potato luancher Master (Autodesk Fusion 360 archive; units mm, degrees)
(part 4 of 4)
sketch "cap_nut .25" plane through (1.5875, 0, 0) normal (-1, 0, 0) x axis (0, -1, 0)
  line L1 (-415.0627, 96.1751) -> (-419.0927, 96.1751)
  line L2 (-410.7414, 131.3694) -> (-415.0627, 96.1751)
  line L3 (-322.4775, 131.3694) -> (-410.7414, 131.3694)
  line L4 (-322.4775, 135.3707) -> (-322.4775, 131.3694)
  line L5 (-330.8961, 135.3707) -> (-322.4775, 135.3707)
  line L6 (-363.9219, 140.5486) -> (-363.9219, 135.3707)
  line L7 (-340.0129, 144.3077) -> (-356.7396, 146.7561)
  line L8 (-329.3961, 159.7411) -> (-329.3961, 153.4836)
  line L9 (-332.3961, 159.7411) -> (-329.3961, 159.7411)
  line L10 (-332.3961, 153.4836) -> (-332.3961, 159.7411)
  line L11 (-356.3051, 149.7245) -> (-339.5784, 147.2761)
  line L12 (-363.9219, 159.7411) -> (-363.9219, 158.5373)
  line L13 (-366.9219, 159.7411) -> (-363.9219, 159.7411)
  line L14 (-366.9219, 158.5373) -> (-366.9219, 159.7411)
  line L15 (-391.2654, 147.2761) -> (-374.5387, 149.7245)
  line L16 (-398.4477, 159.7411) -> (-398.4477, 153.4836)
  line L17 (-401.4477, 159.7411) -> (-398.4477, 159.7411)
  line L18 (-401.4477, 153.4836) -> (-401.4477, 159.7411)
  line L19 (-425.465, 149.168) -> (-408.6888, 147.0857)
  line L20 (-431.7898, 159.7411) -> (-432.0453, 157.5478)
  line L21 (-435.0251, 157.8949) -> (-434.8326, 159.5478)
  line L22 (-445.2444, 150.2873) -> (-443.57, 150.2873)
  line L23 (-443.57, 147.2873) -> (-445.7958, 147.2873)
  line L24 (-439.8464, 116.4962) -> (-437.106, 140.0269)
  line L25 (-450.3271, 110.1718) -> (-448.1574, 109.9191)
  line L26 (-448.5045, 106.9392) -> (-450.1574, 107.1317)
  line L27 (-418.2043, 103.4104) -> (-430.6365, 104.8583)
  line L28 (-419.0927, 96.1751) -> (-418.2043, 103.4104)
  line L29 (-434.1262, 139.6798) -> (-436.8666, 116.1492)
  line L30 (-409.0583, 144.1086) -> (-425.8345, 146.1909)
  line L31 (-374.1042, 146.7561) -> (-390.8309, 144.3077)
  line L32 (-366.9219, 135.3707) -> (-366.9219, 140.5486)
  line L33 (-399.9477, 135.3707) -> (-366.9219, 135.3707)
  line L34 (-414.2801, 135.3707) -> (-399.9477, 135.3707)
  line L35 (-417.8387, 106.3881) -> (-414.2801, 135.3707)
  line L36 (-430.2894, 107.8382) -> (-417.8387, 106.3881)
  line L37 (-433.4597, 110.8166) -> (-433.4597, 103.9608)
  line L38 (-439.397, 114.2444) -> (-433.4597, 110.8166)
  line L39 (-445.3342, 110.8166) -> (-439.397, 114.2444)
  line L40 (-445.3342, 103.9608) -> (-445.3342, 110.8166)
  line L41 (-439.397, 100.5329) -> (-445.3342, 103.9608)
  line L42 (-433.4597, 103.9608) -> (-439.397, 100.5329)
  line L43 (-432.5812, 159.7411) -> (-431.7898, 159.7411)
  line L44 (-445.7958, 147.2873) -> (-445.6908, 148.1427)
  line L45 (-428.6384, 152.2152) -> (-428.6384, 145.3595)
  line L46 (-434.5757, 155.6431) -> (-428.6384, 152.2152)
  line L47 (-440.5129, 152.2152) -> (-434.5757, 155.6431)
  line L48 (-440.5129, 145.3595) -> (-440.5129, 152.2152)
  line L49 (-434.5757, 141.9316) -> (-440.5129, 145.3595)
  line L50 (-428.6384, 145.3595) -> (-434.5757, 141.9316)
  line L51 (-394.0104, 147.9171) -> (-394.0104, 141.0614)
  line L52 (-399.9477, 151.345) -> (-394.0104, 147.9171)
  line L53 (-405.8849, 147.9171) -> (-399.9477, 151.345)
  line L54 (-405.8849, 141.0614) -> (-405.8849, 147.9171)
  line L55 (-399.9477, 137.6335) -> (-405.8849, 141.0614)
  line L56 (-394.0104, 141.0614) -> (-399.9477, 137.6335)
  line L57 (-359.4847, 146.1151) -> (-365.4219, 142.6872)
  line L58 (-359.4847, 152.9708) -> (-359.4847, 146.1151)
  line L59 (-365.4219, 156.3987) -> (-359.4847, 152.9708)
  line L60 (-371.3592, 152.9708) -> (-365.4219, 156.3987)
  line L61 (-371.3592, 146.1151) -> (-371.3592, 152.9708)
  line L62 (-365.4219, 142.6872) -> (-371.3592, 146.1151)
  line L63 (-324.9589, 147.9171) -> (-324.9589, 141.0614)
  line L64 (-330.8961, 151.345) -> (-324.9589, 147.9171)
  line L65 (-336.8334, 147.9171) -> (-330.8961, 151.345)
  line L66 (-336.8334, 141.0614) -> (-336.8334, 147.9171)
  line L67 (-330.8961, 137.6335) -> (-336.8334, 141.0614)
  line L68 (-324.9589, 141.0614) -> (-330.8961, 137.6335)
  line L69 (-363.9219, 135.3707) -> (-330.8961, 135.3707)
  arc A1 centre (-365.4219, 149.543) radius 9.1186 clockwise from (-356.7396, 146.7561) to (-363.9219, 140.5486)
  arc A2 centre (-330.8961, 144.4893) radius 9.1186 clockwise from (-330.8961, 135.3707) to (-340.0129, 144.3077)
  arc A3 centre (-330.8961, 144.4893) radius 9.1186 clockwise from (-329.3961, 153.4836) to (-330.8961, 135.3707)
  arc A4 centre (-330.8961, 144.4893) radius 9.1186 clockwise from (-339.5784, 147.2761) to (-332.3961, 153.4836)
  arc A5 centre (-365.4219, 149.543) radius 9.1186 clockwise from (-363.9219, 158.5373) to (-356.3051, 149.7245)
  arc A6 centre (-365.4219, 149.543) radius 9.1186 clockwise from (-374.5387, 149.7245) to (-366.9219, 158.5373)
  arc A7 centre (-399.9477, 144.4893) radius 9.1186 clockwise from (-398.4477, 153.4836) to (-391.2654, 147.2761)
  arc A8 centre (-399.9477, 144.4893) radius 9.1186 clockwise from (-408.6888, 147.0857) to (-401.4477, 153.4836)
  arc A9 centre (-434.5757, 148.7873) radius 9.1186 clockwise from (-432.0453, 157.5478) to (-425.465, 149.168)
  arc A10 centre (-432.5812, 146.5331) radius 13.208 clockwise from (-434.8326, 159.5478) to (-432.5812, 159.7411)
  arc A11 centre (-434.5757, 148.7873) radius 9.1186 clockwise from (-443.57, 150.2873) to (-435.0251, 157.8949)
  arc A12 centre (-432.5812, 146.5331) radius 13.208 clockwise from (-445.6908, 148.1427) to (-445.2444, 150.2873)
  arc A13 centre (-434.5757, 148.7873) radius 9.1186 clockwise from (-437.106, 140.0269) to (-443.57, 147.2873)
  arc A14 centre (-439.397, 107.3887) radius 9.1186 clockwise from (-448.1574, 109.9191) to (-439.8464, 116.4962)
  arc A15 centre (-437.1427, 109.3831) radius 13.208 clockwise from (-450.1574, 107.1317) to (-450.3271, 110.1718)
  arc A16 centre (-439.397, 107.3887) radius 9.1186 clockwise from (-430.6365, 104.8583) to (-448.5045, 106.9392)
  circle C1 centre (-434.5757, 148.7873) radius 3.325
  arc A17 centre (-434.5757, 148.7873) radius 9.1186 clockwise from (-425.8345, 146.1909) to (-434.1262, 139.6798)
  arc A18 centre (-399.9477, 144.4893) radius 9.1186 clockwise from (-399.9477, 135.3707) to (-409.0583, 144.1086)
  arc A19 centre (-399.9477, 144.4893) radius 9.1186 clockwise from (-390.8309, 144.3077) to (-399.9477, 135.3707)
  arc A20 centre (-365.4219, 149.543) radius 9.1186 clockwise from (-366.9219, 140.5486) to (-374.1042, 146.7561)
  arc A21 centre (-439.397, 107.3887) radius 9.1186 clockwise from (-436.8666, 116.1492) to (-430.2894, 107.8382)
  circle C2 centre (-399.9477, 144.4893) radius 3.325
  circle C3 centre (-365.4219, 149.543) radius 3.325
  circle C4 centre (-439.397, 107.3887) radius 3.325
  circle C5 centre (-330.8961, 144.4893) radius 3.325
  point P46 (-439.397, 107.3887)
  point P71 (-439.397, 107.3887)
  point P34 (-434.5757, 148.7873)
  point P80 (-434.5757, 148.7873)
  point P27 (-399.9477, 144.4893)
  point P87 (-399.9477, 144.4893)
  point P11 (-365.4219, 149.543)
  point P94 (-365.4219, 149.543)
  point P13 (-330.8961, 144.4893)
  point P101 (-330.8961, 144.4893)
  coincident P46 P71
  vertical L37
  coincident P34 P80
  coincident P27 P87
  coincident P11 P94
  coincident P13 P101
  equal L39 L47
  equal L46 L53
  equal L52 L60
  equal L58 L66
  vertical L45
  vertical L51
  vertical L61
  vertical L66
  dimension "d673" distance L39 L42 = 11.8745 (= "( ( 7 / 16 ) * 1 in ) + 0.030 in")
extrude "Extrude17" cut sketch "cap_nut .25" profile of C1 C2 C3 C4 C5 L37 L38 L39 L40 L41 L42 L45 L46 L47 L48 L49 L50 L51 L52 L53 L54 L55 L56 L57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 blind -66.04 from offset -3.9624 (= "( -0.312 / 2 ) * 1 in")
sketch "Sketch12" plane through (-1.5875, 0, 0) normal (1, 0, 0) x axis (0, 1, 0)
  line L1 (436.8666, 116.1492) -> (434.1262, 139.6798)
  line L2 (417.8387, 106.3881) -> (430.2894, 107.8382)
  line L3 (414.2801, 135.3707) -> (417.8387, 106.3881)
  line L4 (399.9477, 135.3707) -> (414.2801, 135.3707)
  line L5 (366.9219, 135.3707) -> (399.9477, 135.3707)
  line L6 (366.9219, 140.5486) -> (366.9219, 135.3707)
  line L7 (390.8309, 144.3077) -> (374.1042, 146.7561)
  line L8 (425.8345, 146.1909) -> (409.0583, 144.1086)
  line L9 (433.6818, 169.4293) -> (435.0251, 157.8949)
  line L10 (433.6818, 169.4293) -> (452.8382, 169.4293)
  line L11 (455.1885, 150.2873) -> (452.8382, 169.4293)
  line L12 (443.57, 150.2873) -> (455.1885, 150.2873)
  line L13 (455.5569, 147.2873) -> (443.57, 147.2873)
  line L14 (459.9761, 111.2955) -> (455.5569, 147.2873)
  line L15 (448.1574, 109.9191) -> (459.9761, 111.2955)
  line L16 (437.106, 140.0269) -> (439.8464, 116.4962)
  line L17 (356.7396, 146.7561) -> (340.0129, 144.3077)
  line L18 (363.9219, 135.3707) -> (363.9219, 140.5486)
  line L19 (330.8961, 135.3707) -> (363.9219, 135.3707)
  line L20 (322.4775, 135.3707) -> (330.8961, 135.3707)
  line L21 (322.4775, 131.3694) -> (322.4775, 135.3707)
  line L22 (410.7414, 131.3694) -> (322.4775, 131.3694)
  line L23 (415.1763, 95.25) -> (410.7414, 131.3694)
  line L24 (419.2063, 95.25) -> (415.1763, 95.25)
  line L25 (418.2043, 103.4104) -> (419.2063, 95.25)
  line L26 (430.6365, 104.8583) -> (418.2043, 103.4104)
  line L27 (460.3417, 108.3178) -> (448.5045, 106.9392)
  line L28 (461.9462, 95.25) -> (460.3417, 108.3178)
  line L29 (465.9763, 95.25) -> (461.9462, 95.25)
  line L30 (456.3769, 173.4306) -> (465.9763, 95.25)
  line L31 (456.3769, 173.4306) -> (405.5769, 173.4306)
  line L32 (322.4775, 173.4306) -> (405.5769, 173.4306)
  line L33 (322.4775, 169.45) -> (322.4775, 173.4306)
  line L34 (322.8085, 169.45) -> (322.4775, 169.45)
  line L35 (322.8085, 169.4293) -> (322.8085, 169.45)
  line L36 (329.3961, 169.4293) -> (322.8085, 169.4293)
  line L37 (329.3961, 153.4836) -> (329.3961, 169.4293)
  line L38 (332.3961, 169.4293) -> (332.3961, 153.4836)
  line L39 (363.9219, 169.4293) -> (332.3961, 169.4293)
  line L40 (363.9219, 158.5373) -> (363.9219, 169.4293)
  line L41 (339.5784, 147.2761) -> (356.3051, 149.7245)
  line L42 (374.5387, 149.7245) -> (391.2654, 147.2761)
  line L43 (366.9219, 169.4293) -> (366.9219, 158.5373)
  line L44 (398.4477, 169.4293) -> (366.9219, 169.4293)
  line L45 (398.4477, 153.4836) -> (398.4477, 169.4293)
  line L46 (408.6888, 147.0857) -> (425.465, 149.168)
  line L47 (401.4477, 169.4293) -> (401.4477, 153.4836)
  line L48 (410.0982, 169.4293) -> (401.4477, 169.4293)
  line L49 (410.0982, 169.4293) -> (430.6615, 169.4293)
  line L50 (432.0453, 157.5478) -> (430.6615, 169.4293)
  circle C1 centre (434.5757, 148.7873) radius 3.325
  arc A1 centre (439.397, 107.3887) radius 9.1186 clockwise from (430.2894, 107.8382) to (436.8666, 116.1492)
  arc A2 centre (365.4219, 149.543) radius 9.1186 clockwise from (374.1042, 146.7561) to (366.9219, 140.5486)
  arc A3 centre (399.9477, 144.4893) radius 9.1186 clockwise from (399.9477, 135.3707) to (390.8309, 144.3077)
  arc A4 centre (399.9477, 144.4893) radius 9.1186 clockwise from (409.0583, 144.1086) to (399.9477, 135.3707)
  arc A5 centre (434.5757, 148.7873) radius 9.1186 clockwise from (434.1262, 139.6798) to (425.8345, 146.1909)
  arc A6 centre (434.5757, 148.7873) radius 9.1186 clockwise from (435.0251, 157.8949) to (443.57, 150.2873)
  arc A7 centre (434.5757, 148.7873) radius 9.1186 clockwise from (443.57, 147.2873) to (437.106, 140.0269)
  arc A8 centre (439.397, 107.3887) radius 9.1186 clockwise from (439.8464, 116.4962) to (448.1574, 109.9191)
  circle C2 centre (399.9477, 144.4893) radius 3.325
  arc A9 centre (330.8961, 144.4893) radius 9.1186 clockwise from (340.0129, 144.3077) to (330.8961, 135.3707)
  arc A10 centre (365.4219, 149.543) radius 9.1186 clockwise from (363.9219, 140.5486) to (356.7396, 146.7561)
  arc A11 centre (439.397, 107.3887) radius 9.1186 clockwise from (448.5045, 106.9392) to (430.6365, 104.8583)
  arc A12 centre (330.8961, 144.4893) radius 9.1186 clockwise from (330.8961, 135.3707) to (329.3961, 153.4836)
  arc A13 centre (365.4219, 149.543) radius 9.1186 clockwise from (356.3051, 149.7245) to (363.9219, 158.5373)
  arc A14 centre (330.8961, 144.4893) radius 9.1186 clockwise from (332.3961, 153.4836) to (339.5784, 147.2761)
  circle C3 centre (365.4219, 149.543) radius 3.325
  circle C4 centre (439.397, 107.3887) radius 3.325
  arc A15 centre (399.9477, 144.4893) radius 9.1186 clockwise from (391.2654, 147.2761) to (398.4477, 153.4836)
  arc A16 centre (365.4219, 149.543) radius 9.1186 clockwise from (366.9219, 158.5373) to (374.5387, 149.7245)
  circle C5 centre (330.8961, 144.4893) radius 3.325
  arc A17 centre (434.5757, 148.7873) radius 9.1186 clockwise from (425.465, 149.168) to (432.0453, 157.5478)
  arc A18 centre (399.9477, 144.4893) radius 9.1186 clockwise from (401.4477, 153.4836) to (408.6888, 147.0857)
  circle C6 centre (330.8961, 144.4893) radius 5.0245
  circle C7 centre (365.4219, 149.543) radius 5.0245
  circle C8 centre (399.9477, 144.4893) radius 5.0245
  circle C9 centre (434.5757, 148.7873) radius 5.0245
  circle C10 centre (439.397, 107.3887) radius 5.0245
  concentric A9 C6
  concentric A2 C7
  concentric A3 C8
  concentric C1 C9
  concentric A1 C10
  equal C7 C8
  equal C8 C9
  equal C9 C10
  equal C6 C7
  dimension "d678" diameter C6 = 10.049 (= "( ( 3 / 8 ) * 1 in ) + 0.06 in - 1 mm")
extrude "Extrude18" cut sketch "Sketch12" profile of C1 C2 C3 C4 C5 C6 C7 C8 C9 C10 blind -35.56 from offset -3.9624 (= "( -0.312 / 2 ) * 1 in")
step "Screw1"
joint "Assemble1" alignAngle 0 alignOffsetX 0 alignOffsetY 0 alignOffsetZ 0
step "Screw2"
joint "Assemble2" alignAngle 0 alignOffsetX 0 alignOffsetY 0 alignOffsetZ 0
step "Screw3"
joint "Assemble3" alignAngle 0 alignOffsetX 0 alignOffsetY 0 alignOffsetZ 0
step "Screw4"
joint "Assemble4" alignAngle 0 alignOffsetX 0 alignOffsetY 0 alignOffsetZ 0
step "Screw5"
joint "Assemble5" alignAngle 0 alignOffsetX 0 alignOffsetY 0 alignOffsetZ 0
sketch "Sketch7" plane through (-1.5875, 0, 0) normal (-1, 0, 0) x axis (0, -1, 0)
  line L1 (-347.7775, 159.7411) -> (-322.7775, 159.7411)
  line L2 (-347.7775, 165.0751) -> (-347.7775, 159.7411)
  line L3 (-322.7775, 165.0751) -> (-347.7775, 165.0751)
  line L4 (-322.7775, 173.45) -> (-322.7775, 165.0751)
  line L5 (-456.3745, 173.45) -> (-322.7775, 173.45)
  line L6 (-466.756, 88.9) -> (-456.3745, 173.45)
  line L7 (-415.956, 88.9) -> (-466.756, 88.9)
  line L8 (-410.7438, 131.35) -> (-415.956, 88.9)
  line L9 (-322.7775, 131.35) -> (-410.7438, 131.35)
  line L10 (-322.7775, 159.7411) -> (-322.7775, 131.35)
  circle C1 centre (-434.5757, 148.7873) radius 3.175
  circle C2 centre (-399.9477, 144.4893) radius 3.175
  circle C3 centre (-365.4219, 149.543) radius 3.175
  circle C4 centre (-330.8961, 144.4893) radius 3.175
  circle C5 centre (-439.397, 107.3887) radius 3.175
  point P12 (-434.5757, 148.7873)
  point P17 (-434.5757, 148.7873)
  point P13 (-399.9477, 144.4893)
  point P18 (-399.9477, 144.4893)
  point P15 (-365.4219, 149.543)
  point P19 (-365.4219, 149.543)
  point P16 (-330.8961, 144.4893)
  point P20 (-330.8961, 144.4893)
  point P14 (-439.397, 107.3887)
  point P21 (-439.397, 107.3887)
  coincident P12 P17
  coincident P13 P18
  coincident P15 P19
  coincident P16 P20
  coincident P14 P21
  dimension "d702" diameter C1 = 6.35
  dimension "d703" diameter C2 = 6.35
  dimension "d704" diameter C3 = 6.35
  dimension "d705" diameter C4 = 6.35
  dimension "d706" diameter C5 = 6.35
extrude "Extrude2" cut sketch "Sketch7" profile of C1 C2 C3 C4 C5 against normal blind 3.175
sketch "fwd upper hole" plane through (0, 0, 0) normal (1, 0, 0) x axis (0, 1, 0)
  line L1 (322.4775, 173.45) -> (322.4775, 169.45)
  line L2 (250.2367, 173.45) -> (322.4775, 173.45)
  line L3 (250.2367, 116.35) -> (250.2367, 173.45)
  line L4 (272.2367, 116.35) -> (250.2367, 116.35)
  line L5 (276.256, 131.35) -> (272.2367, 116.35)
  line L6 (277.081, 131.35) -> (276.256, 131.35)
  line L7 (275.635, 135.35) -> (277.081, 131.35)
  line L8 (273.1866, 135.35) -> (275.635, 135.35)
  line L9 (269.1674, 120.35) -> (273.1866, 135.35)
  line L10 (254.2367, 120.35) -> (269.1674, 120.35)
  line L11 (254.2367, 169.45) -> (254.2367, 120.35)
  line L12 (322.4775, 169.45) -> (254.2367, 169.45)
  line L13 (315.5775, 141.85) -> (319.7775, 137.65)
  line L14 (296.5763, 141.85) -> (315.5775, 141.85)
  line L15 (279.0207, 162.9256) -> (296.5763, 141.85)
  line L16 (263.8509, 141.85) -> (270.1342, 165.3063)
  line L17 (260.0435, 127.6406) -> (263.8509, 141.85)
  line L18 (272.0357, 136.85) -> (268.93, 125.2594)
  line L19 (278.9967, 136.85) -> (272.0357, 136.85)
  line L20 (278.9967, 123.4258) -> (278.9967, 136.85)
  line L21 (313.4688, 135.65) -> (313.4688, 131.35)
  line L22 (319.7775, 135.65) -> (313.4688, 135.65)
  line L23 (319.7775, 137.65) -> (319.7775, 135.65)
  line L24 (287.4207, 168.3994) -> (287.4207, 165.0507)
  line L25 (284.5207, 170.0737) -> (287.4207, 168.3994)
  line L26 (281.6207, 168.3994) -> (284.5207, 170.0737)
  line L27 (281.6207, 165.0507) -> (281.6207, 168.3994)
  line L28 (284.5207, 163.3764) -> (281.6207, 165.0507)
  line L29 (287.4207, 165.0507) -> (284.5207, 163.3764)
  line L30 (332.3961, 159.7411) -> (332.3961, 165.0751)
  line L31 (329.3961, 159.7411) -> (332.3961, 159.7411)
  line L32 (329.3961, 165.0751) -> (329.3961, 159.7411)
  line L33 (332.3961, 165.0751) -> (329.3961, 165.0751)
  line L34 (239.3698, 165.0751) -> (329.3961, 165.0751)
  circle C1 centre (284.5207, 166.7251) radius 4.5
  circle C2 centre (264.4867, 126.45) radius 1.65
  arc A1 centre (264.4867, 126.45) radius 39.2645 clockwise from (270.1342, 165.3063) to (279.0207, 162.9256)
  arc A2 centre (264.4867, 126.45) radius 4.6 clockwise from (268.93, 125.2594) to (260.0435, 127.6406)
  arc A3 centre (274.4187, 51.1532) radius 72.4175 clockwise from (278.9967, 123.4258) to (311.5111, 113.35)
  arc A4 centre (229.7424, 131.35) radius 83.7264 clockwise from (313.4688, 131.35) to (311.5111, 113.35)
  circle C3 centre (284.5207, 166.7251) radius 1.65
  circle C4 centre (284.5207, 166.7251) radius 3
  point P33 (284.5207, 166.7251)
  point P40 (284.5207, 166.7251)
  point P44 (329.3961, 165.0751)
  point P45 (329.3961, 165.0751)
  point P48 (284.5207, 166.7251)
  point P14 (284.5207, 166.7251)
  point P47 (279.0207, 162.9256)
  concentric C1 C3
  coincident P33 P40
  vertical L24
  coincident P44 P45
  perpendicular L3 L34
  tangent C3 L34
  coincident P40 P48
  dimension "d758" diameter C1 = 9
  dimension "d759" diameter C3 = 3.3
  dimension "d762" distance P40 L29 = 2.9 (= "5.8 mm / 2")
  dimension "d767" distance P14 P47 = 5.5 (= "( d758 / 2 ) + 1 mm")
  dimension "d770" diameter C4 = 6
extrude "Extrude19" cut sketch "fwd upper hole" profile of C3 distance 63.5
extrude "Extrude20" add sketch "fwd upper hole" profile of L12 C1 C3 L24 L25 L26 L27 L28 L29 blind -13.248 (= "-0.62 in + 2.5 mm") from offset -2.5
extrude "Extrude21" add sketch "fwd upper hole" profile of L12 C1 C3 L24 L25 L26 L27 L28 L29 blind 12.74 (= "0.60 in - 2.5 mm") from offset 2.5
extrude "Extrude22" cut sketch "fwd upper hole" profile of L12 C3 L24 L25 L26 L27 L28 L29 C4 blind 27.178 from offset 11.5 (= "23 / 2 * 1 mm")
extrude "Extrude23" cut sketch "fwd upper hole" profile of L12 C3 L24 L25 L26 L27 L28 L29 C4 blind -38.1 from offset -11.5 (= "-23 / 2 * 1 mm")
work_plane "WorkPlane26" AlongDistance 173.4312
sketch "rel. arm" plane through (-21.6421, 0, 39.0435) normal (0.4848, 0, -0.8746) x axis (0, 1, 0)
  line L1 (-18.2143, -41.7968) -> (-43.5756, -54.6337)
  line L2 (-46.6067, -41.9337) -> (-23.9497, -30.4657)
  line L3 (-69.7366, -42.4813) -> (-48.9008, -42.4813)
  line L4 (-68.326, -34.4813) -> (-69.7366, -42.4813)
  line L5 (-45.8698, -55.1813) -> (-69.626, -55.1813)
  line L6 (-53.3478, -62.9923) -> (-49.4885, -84.8797)
  line L7 (46.7086, -45.3497) -> (-53.3478, -62.9923)
  line L8 (50.568, -67.237) -> (46.7086, -45.3497)
  line L9 (-49.4885, -84.8797) -> (50.568, -67.237)
  line L10 (-55.5532, -50.4852) -> (-53.3478, -62.9923)
  line L11 (-34.5873, -59.6843) -> (-36.7926, -47.1773)
  line L12 (-34.5873, -59.6843) -> (-49.4885, -84.8797)
  arc A1 centre (-45.8698, -50.1012) radius 5.08 clockwise from (-43.5756, -54.6337) to (-45.8698, -55.1813)
  arc A2 centre (-48.9008, -37.4013) radius 5.08 clockwise from (-46.6067, -41.9337) to (-48.9008, -42.4813)
  arc A3 centre (-68.326, -50.7312) radius 16.25 clockwise from (-82.326, -42.4813) to (-68.326, -34.4813)
  arc A4 centre (-69.626, -42.4813) radius 12.7 clockwise from (-69.626, -55.1813) to (-82.326, -42.4813)
  circle C1 centre (-46.1729, -48.8313) radius 3.175
  circle C2 centre (-46.1729, -48.8313) radius 9.525
  arc A5 centre (-27.3278, -49.3167) radius 8.9495 clockwise from (-25.7737, -58.1302) to (-36.1413, -50.8708)
  arc A6 centre (-21.082, -36.1313) radius 6.35 clockwise from (-23.9497, -30.4657) to (-18.2143, -41.7968)
  circle C3 centre (-21.082, -36.1313) radius 3.175
  point P22 (-55.5532, -50.4852)
  point P23 (-36.7926, -47.1773)
  point P24 (-34.5873, -59.6843)
  point P27 (-25.7737, -58.1302)
  point P26 (-36.1413, -50.8708)
  point P17 (-49.4885, -84.8797)
  point P18 (-53.3478, -62.9923)
  point P21 (-46.1729, -48.8313)
  point P20 (50.568, -67.237)
  perpendicular L6 L7
  parallel L6 L8
  parallel L7 L9
  concentric C1 C2
  coincident C2 P22
  perpendicular L7 L10
  tangent C2 L10
  coincident C2 P23
  coincident L7 P24
  tangent C2 L11
  perpendicular L7 L11
  coincident L7 P27
  coincident L11 P26
  tangent L11 A5
  tangent L7 A5
  coincident L1 P26
  dimension "d713" distance P17 P18 = 22.225
  dimension "d714" diameter C2 = 19.05
  dimension "d715" distance L7 P21 = 12.7
  dimension "d716" angle L5 L10 = 100
  dimension "d717" distance P17 P20 = 101.6
face "Face1" sketch "rel. arm"
fillet "Fillet1" radius 27.94
position "Position12"
sketch "Sketch59" plane through (-21.0604, 0, 37.9939) normal (-0.4848, 0, 0.8746) x axis (0, -1, 0)
  line L1 (55.5532, -50.4852) -> (54.3402, -57.3641)
  line L2 (36.1413, -50.8708) -> (36.7926, -47.1773)
  line L3 (-46.7086, -45.3497) -> (25.7737, -58.1302)
  line L4 (-50.568, -67.237) -> (-46.7086, -45.3497)
  line L5 (21.973, -80.0279) -> (-50.568, -67.237)
  circle C1 centre (46.1729, -48.8313) radius 3.175
  arc A1 centre (26.8247, -52.5124) radius 27.94 clockwise from (54.3402, -57.3641) to (21.973, -80.0279)
  arc A2 centre (46.1729, -48.8313) radius 9.525 clockwise from (36.7926, -47.1773) to (55.5532, -50.4852)
  arc A3 centre (27.3278, -49.3167) radius 8.9495 clockwise from (36.1413, -50.8708) to (25.7737, -58.1302)
  circle C2 centre (46.1729, -48.8313) radius 9.525
  circle C3 centre (46.1729, -48.8313) radius 3.475
  concentric C1 C2
  dimension "d724" = 0.3
place_component sketch "Sketch59"
extrude "Extrude1" new body sketch "Sketch59" profile of A2 C2 C3 along normal blind 1.2
sketch "rel spring anchor" plane through (-64.597, 13.023, -35.8067) normal (-0.8613, 0.1736, -0.4774) x axis (-0.1976, -0.9803, 0)
  line L1 (39.5345, 39.8359) -> (39.2303, 36.6755)
  line L2 (-33.7866, 46.8934) -> (39.5345, 39.8359)
  line L3 (-34.0908, 43.733) -> (-33.7866, 46.8934)
  line L4 (39.2303, 36.6755) -> (-34.0908, 43.733)
  line L5 (21.4358, 41.578) -> (22.1659, 49.1629)
  line L6 (12.1191, 52.7294) -> (19.8382, 51.9864)
  line L7 (4.4452, 46.4031) -> (12.1191, 52.7294)
  line L8 (4.141, 43.2427) -> (4.4452, 46.4031)
  circle C1 centre (19.5903, 49.4108) radius 1
  circle C2 centre (19.5903, 49.4108) radius 2.5875
  point P9 (21.4358, 41.578)
  point P12 (4.141, 43.2427)
  point P8 (19.8382, 51.9864)
  point P7 (22.1659, 49.1629)
  point P6 (19.5903, 49.4108)
  point P11 (4.4452, 46.4031)
  coincident L2 P9
  perpendicular L2 L5
  perpendicular L5 L6
  coincident L2 P12
  perpendicular L2 L8
  coincident P8 C2
  tangent L6 C2
  coincident P7 C2
  tangent L5 C2
  dimension "d734" angle L7 L8 = 135
  dimension "d735" = 1.5875 (= "( 1 / 16 ) * 1 in")
  dimension "d751" distance L2 P6 = 7.62
  dimension "d752" diameter C1 = 2
  dimension "d753" distance P11 P12 = 3.175
place_component sketch "rel spring anchor"
face "Face1" sketch "rel spring anchor"
sketch "arming handle" plane through (-29.1846, 0, 52.6504) normal (0.4848, 0, -0.8746) x axis (0, 1, 0)
  line L1 (-118.3323, -14.605) -> (-207.2323, -14.605)
  line L2 (-118.3323, 14.605) -> (-118.3323, -14.605)
  line L3 (-207.2323, 14.605) -> (-118.3323, 14.605)
  line L4 (-207.2323, -14.605) -> (-207.2323, 14.605)
  line L5 (22.5, 0) -> (1.75, 0)
  line L6 (-123.3323, 9.605) -> (-123.3323, -9.605)
  line L7 (-205.0949, 9.605) -> (-123.3323, 9.605)
  line L8 (-123.3323, -9.605) -> (-205.0949, -9.605)
  line L9 (-108.8073, 14.605) -> (-118.3323, 14.605)
  line L10 (-108.8073, -14.605) -> (-108.8073, 14.605)
  line L11 (-118.3323, -14.605) -> (-108.8073, -14.605)
  line L12 (-118.3323, 14.605) -> (-118.3323, -14.605)
  line L13 (-136.0323, -9.605) -> (-136.0323, 9.605)
  line L14 (-141.0323, -9.605) -> (-141.0323, 9.605)
  line L15 (-192.3949, -9.605) -> (-192.3949, 9.605)
  line L16 (-187.3949, -9.605) -> (-187.3949, 9.605)
  line L17 (-161.7136, -9.605) -> (-161.7136, 9.605)
  line L18 (-166.7136, -9.605) -> (-166.7136, 9.605)
  line L19 (-187.3949, 0) -> (-166.7136, 0)
  line L20 (-141.0323, 0) -> (-161.7136, 0)
  circle C1 centre (-95.6445, -13.1559) radius 1.61
  circle C2 centre (-38.0048, 0) radius 1.61
  circle C3 centre (-95.6445, 13.1559) radius 1.61
  circle C4 centre (-75.0731, -29.561) radius 1.61
  circle C5 centre (-49.421, 23.7061) radius 1.61
  circle C6 centre (-75.0731, 29.561) radius 1.61
  circle C7 centre (-49.421, -23.7061) radius 1.61
  circle C8 centre (-68.326, 0) radius 20.1613
  circle C9 centre (-68.326, 0) radius 40.4813
  circle C10 centre (-95.6445, -13.1559) radius 1.61
  circle C11 centre (-38.0048, 0) radius 1.61
  circle C12 centre (-95.6445, 13.1559) radius 1.61
  circle C13 centre (-75.0731, -29.561) radius 1.61
  circle C14 centre (-49.421, 23.7061) radius 1.61
  circle C15 centre (-75.0731, 29.561) radius 1.61
  circle C16 centre (-49.421, -23.7061) radius 1.61
  circle C17 centre (-68.326, 0) radius 20.1613
  circle C18 centre (-68.326, 0) radius 40.4813
  circle C19 centre (-68.326, 0) radius 40.4813
  arc A1 centre (-193.6115, 0) radius 19.9707 clockwise from (-207.2323, -14.605) to (-207.2323, 14.605)
  arc A2 centre (-193.6115, 0) radius 14.9707 clockwise from (-205.0949, -9.605) to (-205.0949, 9.605)
  arc A3 centre (-118.3323, 14.605) radius 1.5875 clockwise from (-116.7448, 14.605) to (-119.9198, 14.605)
  arc A4 centre (-121.5492, 32.2008) radius 21.7249 clockwise from (-102.9615, 20.955) to (-108.8073, 14.605)
  arc A5 centre (-108.8073, 14.605) radius 1.5875 clockwise from (-107.5563, 15.5824) to (-110.3948, 14.605)
  arc A6 centre (-108.8073, -14.605) radius 1.5875 clockwise from (-110.3948, -14.605) to (-107.5563, -15.5824)
  arc A7 centre (-118.3323, -14.605) radius 1.5875 clockwise from (-119.9198, -14.605) to (-116.7448, -14.605)
  arc A8 centre (-121.5492, -32.2008) radius 21.7249 clockwise from (-108.8073, -14.605) to (-102.9615, -20.955)
  point P16 (-207.2323, 0)
  point P27 (-213.5823, 0)
  point P11 (-118.3323, -14.605)
  point P12 (-118.3323, 14.605)
  point P36 (-118.3323, 14.605)
  point P37 (-119.9198, 14.605)
  point P38 (-116.7448, 14.605)
  point P39 (-102.9615, 20.955)
  point P33 (-108.8073, 14.605)
  point P41 (-108.8073, 14.605)
  point P42 (-110.3948, 14.605)
  point P43 (-107.5563, 15.5824)
  point P48 (-119.9198, -14.605)
  point P49 (-116.7448, -14.605)
  point P45 (-110.3948, -14.605)
  point P46 (-107.5563, -15.5824)
  point P51 (-108.8073, -14.605)
  point P52 (-102.9615, -20.955)
  point P53 (-136.0323, 9.605)
  point P54 (-136.0323, -9.605)
  point P55 (-141.0323, 9.605)
  point P56 (-141.0323, -9.605)
  point P57 (-192.3949, 9.605)
  point P58 (-192.3949, -9.605)
  point P59 (-187.3949, 9.605)
  point P60 (-187.3949, -9.605)
  point P61 (-161.7136, 9.605)
  point P62 (-161.7136, -9.605)
  point P63 (-166.7136, 9.605)
  point P64 (-166.7136, -9.605)
  point P65 (-166.7136, 0)
  point P66 (-187.3949, 0)
  point P67 (-161.7136, 0)
  point P68 (-141.0323, 0)
  point P10 (-207.2323, -14.605)
  point P34 (-108.8073, -14.605)
  point P35 (-118.3323, -14.605)
  point P29 (-123.3323, 9.605)
  point P30 (-205.0949, 9.605)
  horizontal L1
  vertical L2
  horizontal L3
  vertical L4
  midpoint L4 P16
  coincident L5 P16
  midpoint A1 P27
  horizontal L9
  vertical L10
  horizontal L11
  vertical L12
  coincident P11 L11
  coincident P12 P36
  tangent C19 L10
  coincident L3 P37
  coincident L9 P38
  tangent C19 A4
  coincident C19 P39
  coincident P33 P41
  coincident L9 P42
  coincident A4 P43
  symmetric L5 P37 P48
  symmetric L5 P38 P49
  symmetric L5 A3 A7
  symmetric L5 P42 P45
  symmetric L5 P43 P46
  symmetric L5 A5 A6
  symmetric L5 P33 P51
  symmetric L5 P39 P52
  symmetric L5 A4 A8
  coincident L7 P53
  coincident L8 P54
  perpendicular L8 L13
  coincident L7 P55
  coincident L8 P56
  perpendicular L8 L14
  coincident L7 P57
  coincident L8 P58
  perpendicular L8 L15
  coincident L7 P59
  coincident L8 P60
  perpendicular L8 L16
  coincident L7 P61
  coincident L8 P62
  perpendicular L8 L17
  coincident L7 P63
  coincident L8 P64
  perpendicular L8 L18
  midpoint L18 P65
  midpoint L16 P66
  midpoint L17 P67
  midpoint L14 P68
  equal L19 L20
  dimension "d777" distance P11 P12 = 29.21
  dimension "d778" distance P10 P11 = 88.9
  dimension "d780" distance P16 P27 = 6.35
  dimension "d783" = -5
  dimension "d784" distance P34 P35 = 9.525 (= "( 3 / 8 ) * 1 in")
  dimension "d785" radius A3 = 1.5875 (= "( 1 / 16 ) * 1 in")
  dimension "d786" distance L9 P39 = 6.35
  dimension "d787" radius A5 = 1.5875 (= "d785")
  dimension "d788" distance L13 L14 = 5
  dimension "d789" distance P29 L13 = 12.7
  dimension "d790" distance L15 L16 = 5 (= "d788")
  dimension "d791" distance P30 L15 = 12.7 (= "d789")
  dimension "d792" distance L17 L18 = 5 (= "d788")
face "Face1" sketch "arming handle"
remove_instance "RemoveInstance1"
work_plane "WorkPlane1"
sketch "Sketch8" plane through (0, 0, 0) normal (1, 0, 0) x axis (0, 1, 0)
  line L1 (-50.0924, 49.403) -> (-40.3316, 49.403)
  line L2 (-50.0924, 52.578) -> (-50.0924, 49.403)
  line L3 (-40.3316, 52.578) -> (-50.0924, 52.578)
  line L4 (-40.3316, 49.403) -> (-40.3316, 52.578)
  line L5 (-45.212, 94.1887) -> (-45.212, 52.578)
  line L6 (-57.912, 52.578) -> (-55.372, 65.928)
  line L7 (-85.6932, 52.578) -> (-4.7308, 52.578)
  line L8 (-45.212, 65.928) -> (-55.372, 65.928)
  line L9 (-48.0335, 58.928) -> (-43.1877, 58.928)
  line L10 (-47.2959, 61.928) -> (-42.2949, 61.928)
  line L11 (-45.212, 61.928) -> (-51.854, 61.928)
  line L12 (-51.854, 52.578) -> (-51.854, 61.928)
  line L13 (-50.0924, 52.578) -> (-51.354, 52.578)
  point P6 (-45.212, 52.578)
  point P12 (-45.212, 65.928)
  point P9 (-57.912, 52.578)
  point P18 (-51.854, 61.928)
  point P19 (-51.854, 52.578)
  point P8 (-55.372, 65.928)
  point P4 (-50.0924, 52.578)
  point P20 (-51.354, 52.578)
  midpoint L3 P6
  vertical L5
  coincident L5 P12
  coincident P9 L7
  horizontal L8
  perpendicular L5 L9
  horizontal L10
  coincident L11 P18
  coincident L7 P19
  perpendicular L7 L12
  dimension "d793" distance L5 P9 = 12.7
  dimension "d794" distance P8 P12 = 10.16
  dimension "d796" distance P4 L9 = 6.35
  dimension "d797" distance L9 L10 = 3
  dimension "d799" distance P12 L10 = 4
  dimension "d800" distance P19 P20 = 0.5
revolve "Revolve1" sketch "Sketch8" AlongAngle 360
sketch "Sketch9" plane through (0, 0, 65.928) normal (0, 0, 1) x axis (-1, 0, 0)
  line L1 (3.729, 40.3316) -> (3.729, 50.0924)
  line L2 (13.7445, 62.1652) -> (13.7445, 56.8027)
  line L3 (2.9845, 62.1652) -> (13.7445, 62.1652)
  line L4 (2.9845, 56.8027) -> (2.9845, 62.1652)
  line L5 (13.7445, 56.8027) -> (2.9845, 56.8027)
  line L6 (-11.5907, 31.4675) -> (-16.9532, 31.4675)
  line L7 (-11.5907, 42.2275) -> (-11.5907, 31.4675)
  line L8 (-16.9532, 42.2275) -> (-11.5907, 42.2275)
  line L9 (-16.9532, 31.4675) -> (-16.9532, 42.2275)
  line L10 (3.729, 50.0924) -> (3.729, 40.3316)
  line L11 (-3.729, 40.3316) -> (-3.729, 50.0924)
  circle C1 centre (0, 45.212) radius 10.16
  circle C2 centre (0, 14.8908) radius 1.61
  circle C3 centre (29.561, 51.9591) radius 1.61
  circle C4 centre (-13.1559, 72.5305) radius 1.61
  circle C5 centre (-29.561, 51.9591) radius 1.61
  circle C6 centre (13.1559, 72.5305) radius 1.61
  circle C7 centre (23.7061, 26.307) radius 1.61
  circle C8 centre (-23.7061, 26.307) radius 1.61
  arc A1 centre (0, 45.212) radius 6.142 clockwise from (-3.729, 50.0924) to (3.729, 50.0924)
  arc A2 centre (0, 45.212) radius 6.142 clockwise from (3.729, 40.3316) to (-3.729, 40.3316)
  circle C9 centre (0, 45.212) radius 40.4812
  circle C10 centre (0, 45.212) radius 2.5908
  concentric A1 C10
  dimension "d805" diameter C10 = 5.1816 (= "( ( 0.199 + 0.209 ) / 2 ) * 1 in")
extrude "Extrude1" cut sketch "Sketch9" profile of L1 L10 A1 L11 A2 along a picked direction blind -22.86 from offset -3
extrude "Extrude2" cut sketch "Sketch9" profile of C10 along a picked direction blind -3
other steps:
base_feature "Base Feature1"
base_feature "Base Feature1"
base_feature "Base Feature1"
derived_base_feature "Derived Base Feature"
extrude "Extrude2" cut sketch "Sketch4" profile of C4 C5 C6 C7 C8 C9 C10 against normal blind 10.668
extrude "Extrude1" cut sketch "Sketch4" profile of C4 C5 C6 C7 C8 C9 C10 against normal blind 10.668
base_feature "Base Feature1"
extrude "Extrude1" cut sketch "Sketch46" profile of C1 against normal blind 5.175 (magnitude of "-0.125 in - 2 mm")
thread "Thread1" ThreadOffset 0 ThreadDepth 10.0076
create_component "CreateComponent1"
remove_body "RemoveBody1"
create_component "CreateComponent2"
create_component "CreateComponent1"
remove_body "RemoveBody1"
create_component "CreateComponent2"
remove_body "RemoveBody1"
create_component "CreateComponent3"
create_component "CreateComponent4"
remove_instance "RemoveInstance1"
create_component "CreateComponent1"
create_component "CreateComponent3"
create_component "CreateComponent1"
create_component "CreateComponent2"
create_component "CreateComponent3"
joint_origin "JointOrigin1"
joint_origin "JointOrigin2"
joint_origin "JointOrigin3"
joint_origin "JointOrigin4"
joint_origin "JointOrigin5"
joint_origin "JointOrigin6"
joint_origin "JointOrigin7"
create_component "CreateComponent5"
joint_origin "JointOrigin1"
joint_origin "JointOrigin2"
create_component "CreateComponent5"
create_component "CreateComponent3" sketch "Sketch4"
create_component "CreateComponent6"
create_component "CreateComponent7"
create_component "CreateComponent8"
create_component "CreateComponent2"
create_component "CreateComponent1" sketch "Sketch2"
create_component "CreateComponent2" sketch "Sketch3"
create_component "CreateComponent3"
remove_body "RemoveBody1"
create_component "CreateComponent3"
create_component "CreateComponent4"
create_component "CreateComponent5"
create_component "CreateComponent11"
create_component "CreateComponent1"
create_component "CreateComponent1"
create_component "CreateComponent1"
create_component "CreateComponent13"
create_component "CreateComponent2"
joint_origin "JointOrigin1"
joint_origin "JointOrigin1"
extrude "Extrude6" cut sketch "trig piv bolt" profile of C2 along normal blind 43.18 and against normal blind 20.32
joint_origin "JointOrigin1"
joint_origin "JointOrigin2"
joint_origin "JointOrigin3"
joint_origin "JointOrigin4"
joint_origin "JointOrigin5"
create_component "CreateComponent2"
create_component "CreateComponent3" sketch "Sketch59"
create_component "CreateComponent4" sketch "rel spring anchor"
create_component "CreateComponent6"
create_component "CreateComponent7"
named bodies: "right", "left", "left (1)", "right (1)", "top", "back", "face"

design "Broached Hexagon Socket Head Cap Screw ANSI B18.3.1M - M3x0.5 x 25 Steel Grade 2 Zinc"
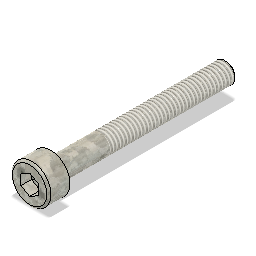
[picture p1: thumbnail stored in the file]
description: Broached Hexagon Socket Head Cap Screw ANSI B18.3.1M - M3x0.5 x 25
part number: arrangementsContainer
parameter "adsk_nomlen" = 25
parameter "adsk_headh" = 3
parameter "adsk_headdia" = 5.5
parameter "adsk_nomdia" = 3
parameter "adsk_waflat" = 2.5
parameter "adsk_keyend" = 1.5
parameter "adsk_thrlen" = 18
parameter "adsk_startlen" = 0.3067
parameter "adsk_endpointdia" = 2.3866
sketch "Sketch1" plane through (0, 0, 0) normal (0, 1, 0) x axis (1, 0, 0)
  line L1 (-1.5, 25) -> (-1.5, 0)
  line L2 (0, 25) -> (-1.5, 25)
  line L3 (0, -3) -> (0, 25)
  line L4 (-2.75, 0) -> (-1.5, 0)
  line L5 (-2.75, -3) -> (-2.75, 0)
  line L6 (0, -3) -> (-2.75, -3)
  point P1 (0, 0)
  point P4 (0, 25)
  point P7 (0, -3)
  point P5 (-2.75, 0)
  point P6 (-2.75, -3)
  perpendicular L1 L2
  collinear P1 P4 P7
  perpendicular L1 L4
  coincident P1 L4
  vertical L1
  vertical L3
  parallel L3 L5
  coincident L3 P7
  perpendicular L3 L6
  dimension "d9" = 3 (= "adsk_nomdia")
  dimension "d66" = 5.5 (= "adsk_headdia")
  dimension "d68" distance P1 P4 = 25 (= "adsk_nomlen")
  dimension "d79" distance P5 P6 = 3 (= "adsk_headh")
revolve "Revolve1" sketch "Sketch1" AlongAngle 360
work_plane "WorkPlane1" AlongDistance 3 (= "adsk_headh")
sketch "Sketch6" plane through (0, 0, 3) normal (0, 0, 1) x axis (1, 0, 0)
  line L1 (1.25, 0) -> (-1.25, 0)
  line L2 (-1.25, 0.7217) -> (0, 0)
  line L3 (-1.25, 0.7217) -> (-1.25, -0.7217)
  line L4 (0, 0) -> (-1.25, -0.7217)
  point P1 (0, 0)
  point P4 (0, 0)
  point P2 (-1.25, 0)
  point P5 (-1.25, 0.7217)
  point P7 (-1.25, 0.7217)
  point P8 (0, 0)
  point P3 (1.25, 0)
  horizontal L1
  midpoint P1 L1
  coincident P1 P4
  perpendicular L1 L3
  midpoint P2 L3
  coincident P5 P7
  coincident P1 P8
  dimension "d72" distance P2 P3 = 2.5 (= "adsk_waflat")
  dimension "d100" angle L1 L2 = 150
extrude "Extrude1" cut sketch "Sketch6" profile of L2 L3 L4 no distance stored
circular_pattern "C-Pattern1" TotalAngle 360
extrude "Extrude2" cut of existing geometry no distance stored taper -85
thread "Thread2" ThreadOffset 0 ThreadLength 18 (= "adsk_thrlen")
fillet "Fillet4" radius 0.3 (= "adsk_nomdia * 0.1")
sketch "Sketch7" plane through (0, 0, 0) normal (0, 1, 0) x axis (1, 0, 0)
  line L1 (-1.53, 24.6933) -> (-1.53, 25)
  line L2 (-1.1933, 25) -> (-1.53, 24.6933)
  line L3 (0, -3) -> (0, 25)
  line L4 (0, 25) -> (-1.53, 25)
  point P5 (0, 25)
  point P7 (0, 25)
  point P4 (-1.1933, 25)
  point P3 (-1.53, 24.6933)
  point P1 (0, 0)
  coincident P5 P7
  perpendicular L3 L4
  coincident P4 L4
  perpendicular L1 L4
  dimension "d92" distance P3 P4 = 0.3067 (= "adsk_startlen")
  dimension "d98" distance P1 P4 = 1.1933 (= "adsk_endpointdia / 2")
  dimension "d99" distance P1 L1 = 1.53 (= "adsk_nomdia * 0.51")
revolve "Revolve3" sketch "Sketch7" AlongAngle 360
joint_origin "JointOrigin2" OffsetX 0 OffsetY 0 OffsetZ 0 AngleZ 0

design "Hexagon Socket Head Cap Screw ANSI B18.3 - 1/4-28 UNF x 0.75 Steel Grade 2 Plain"
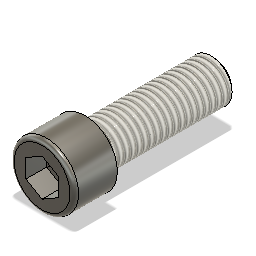
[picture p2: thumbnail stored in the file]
description: Hexagon Socket Head Cap Screw ANSI B18.3 - 1/4-28 UNF x 0.75
part number: arrangementsContainer
parameter "adsk_nomlen" = 19.05
parameter "adsk_headh" = 6.35
parameter "adsk_headdia" = 9.525
parameter "adsk_nomdia" = 6.35
parameter "adsk_waflat" = 4.7752
parameter "adsk_keyend" = 3.048
parameter "adsk_thrlen" = 17.6891
parameter "adsk_startlen" = 0.541
parameter "adsk_endpointdia" = 5.268
sketch "Sketch1" plane through (0, 0, 0) normal (0, 1, 0) x axis (1, 0, 0)
  line L1 (-3.175, 19.05) -> (-3.175, 0)
  line L2 (0, 19.05) -> (-3.175, 19.05)
  line L3 (0, -6.35) -> (0, 19.05)
  line L4 (-4.7625, 0) -> (-3.175, 0)
  line L5 (-4.7625, -6.35) -> (-4.7625, 0)
  line L6 (0, -6.35) -> (-4.7625, -6.35)
  point P1 (0, 0)
  point P4 (0, 19.05)
  point P7 (0, -6.35)
  point P5 (-4.7625, 0)
  point P6 (-4.7625, -6.35)
  perpendicular L1 L2
  collinear P1 P4 P7
  perpendicular L1 L4
  coincident P1 L4
  vertical L1
  vertical L3
  parallel L3 L5
  coincident L3 P7
  perpendicular L3 L6
  dimension "d9" = 6.35 (= "adsk_nomdia")
  dimension "d66" = 9.525 (= "adsk_headdia")
  dimension "d68" distance P1 P4 = 19.05 (= "adsk_nomlen")
  dimension "d79" distance P5 P6 = 6.35 (= "adsk_headh")
revolve "Revolve1" sketch "Sketch1" AlongAngle 360
work_plane "WorkPlane1" AlongDistance 6.35 (= "adsk_headh")
sketch "Sketch6" plane through (0, 0, 6.35) normal (0, 0, 1) x axis (1, 0, 0)
  line L1 (2.3876, 0) -> (-2.3876, 0)
  line L2 (-2.3876, 1.3785) -> (0, 0)
  line L3 (-2.3876, 1.3785) -> (-2.3876, -1.3785)
  line L4 (0, 0) -> (-2.3876, -1.3785)
  point P1 (0, 0)
  point P4 (0, 0)
  point P2 (-2.3876, 0)
  point P5 (-2.3876, 1.3785)
  point P7 (-2.3876, 1.3785)
  point P8 (0, 0)
  point P3 (2.3876, 0)
  horizontal L1
  midpoint P1 L1
  coincident P1 P4
  perpendicular L1 L3
  midpoint P2 L3
  coincident P5 P7
  coincident P1 P8
  dimension "d72" distance P2 P3 = 4.7752 (= "adsk_waflat")
  dimension "d106" angle L1 L2 = 150
extrude "Extrude1" cut sketch "Sketch6" profile of L2 L3 L4 no distance stored
circular_pattern "C-Pattern1" TotalAngle 360
extrude "Extrude2" cut of existing geometry no distance stored taper -85
thread "Thread2" ThreadOffset 0 ThreadLength 17.6891 (= "adsk_thrlen")
fillet "Fillet4" radius 0.635 (= "adsk_nomdia * 0.1")
sketch "Sketch7" plane through (0, 0, 0) normal (0, 1, 0) x axis (1, 0, 0)
  line L1 (-3.2385, 18.509) -> (-3.2385, 19.05)
  line L2 (-2.634, 19.05) -> (-3.2385, 18.509)
  line L3 (0, -6.35) -> (0, 19.05)
  line L4 (0, 19.05) -> (-3.2385, 19.05)
  point P5 (0, 19.05)
  point P7 (0, 19.05)
  point P4 (-2.634, 19.05)
  point P1 (0, 0)
  point P3 (-3.2385, 18.509)
  coincident P5 P7
  perpendicular L3 L4
  coincident P4 L4
  perpendicular L1 L4
  dimension "d103" distance P1 L1 = 3.2385 (= "adsk_nomdia * 0.51")
  dimension "d104" distance P3 P4 = 0.541 (= "adsk_startlen")
  dimension "d105" distance P1 P4 = 2.634 (= "adsk_endpointdia / 2")
revolve "Revolve3" sketch "Sketch7" AlongAngle 360
joint_origin "JointOrigin2" OffsetX 0 OffsetY 0 OffsetZ 0 AngleZ 0

design "Socket Head Cap Screw JIS B 1176 - M3 x 0.5 x 20 Steel 4.6 Plain"
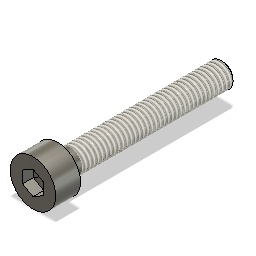
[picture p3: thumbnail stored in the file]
description: Socket Head Cap Screw JIS B 1176 - M3 x 0.5 x 20
part number: arrangementsContainer
parameter "adsk_nomlen" = 20
parameter "adsk_headh" = 3
parameter "adsk_headdia" = 5.5
parameter "adsk_nomdia" = 3
parameter "adsk_waflat" = 2.5
parameter "adsk_keyend" = 1.3
parameter "adsk_thrlen" = 18.5
parameter "adsk_startlen" = 0.3067
parameter "adsk_endpointdia" = 2.3866
sketch "Sketch1" plane through (0, 0, 0) normal (0, 1, 0) x axis (1, 0, 0)
  line L1 (-1.5, 20) -> (-1.5, 0)
  line L2 (0, 20) -> (-1.5, 20)
  line L3 (0, -3) -> (0, 20)
  line L4 (-2.75, 0) -> (-1.5, 0)
  line L5 (-2.75, -3) -> (-2.75, 0)
  line L6 (0, -3) -> (-2.75, -3)
  point P1 (0, 0)
  point P4 (0, 20)
  point P7 (0, -3)
  point P5 (-2.75, 0)
  point P6 (-2.75, -3)
  perpendicular L1 L2
  collinear P1 P4 P7
  perpendicular L1 L4
  coincident P1 L4
  vertical L1
  vertical L3
  parallel L3 L5
  coincident L3 P7
  perpendicular L3 L6
  dimension "d9" = 3 (= "adsk_nomdia")
  dimension "d66" = 5.5 (= "adsk_headdia")
  dimension "d68" distance P1 P4 = 20 (= "adsk_nomlen")
  dimension "d79" distance P5 P6 = 3 (= "adsk_headh")
revolve "Revolve1" sketch "Sketch1" AlongAngle 360
work_plane "WorkPlane1" AlongDistance 3 (= "adsk_headh")
sketch "Sketch6" plane through (0, 0, 3) normal (0, 0, 1) x axis (1, 0, 0)
  line L1 (1.25, 0) -> (-1.25, 0)
  line L2 (-1.25, 0.7217) -> (0, 0)
  line L3 (-1.25, 0.7217) -> (-1.25, -0.7217)
  line L4 (0, 0) -> (-1.25, -0.7217)
  point P1 (0, 0)
  point P4 (0, 0)
  point P2 (-1.25, 0)
  point P5 (-1.25, 0.7217)
  point P7 (-1.25, 0.7217)
  point P8 (0, 0)
  point P3 (1.25, 0)
  horizontal L1
  midpoint P1 L1
  coincident P1 P4
  perpendicular L1 L3
  midpoint P2 L3
  coincident P5 P7
  coincident P1 P8
  dimension "d72" distance P2 P3 = 2.5 (= "adsk_waflat")
  dimension "d97" angle L1 L2 = 150
extrude "Extrude1" cut sketch "Sketch6" profile of L2 L3 L4 no distance stored
circular_pattern "C-Pattern1" TotalAngle 360
extrude "Extrude2" cut of existing geometry no distance stored taper -85
thread "Thread2" ThreadOffset 0 ThreadLength 18.5 (= "adsk_thrlen")
sketch "Sketch7" plane through (0, 0, 0) normal (0, 1, 0) x axis (1, 0, 0)
  line L1 (-1.53, 19.6933) -> (-1.53, 20)
  line L2 (-1.1933, 20) -> (-1.53, 19.6933)
  line L3 (0, -3) -> (0, 20)
  line L4 (0, 20) -> (-1.53, 20)
  point P5 (0, 20)
  point P7 (0, 20)
  point P4 (-1.1933, 20)
  point P1 (0, 0)
  point P3 (-1.53, 19.6933)
  coincident P5 P7
  perpendicular L1 L4
  coincident P4 L4
  perpendicular L3 L4
  dimension "d94" distance P1 L1 = 1.53 (= "adsk_nomdia * 0.51")
  dimension "d95" distance P3 P4 = 0.3067 (= "adsk_startlen")
  dimension "d96" distance P1 P4 = 1.1933 (= "adsk_endpointdia / 2")
revolve "Revolve3" sketch "Sketch7" AlongAngle 360
joint_origin "JointOrigin2" OffsetX 0 OffsetY 0 OffsetZ 0 AngleZ 0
